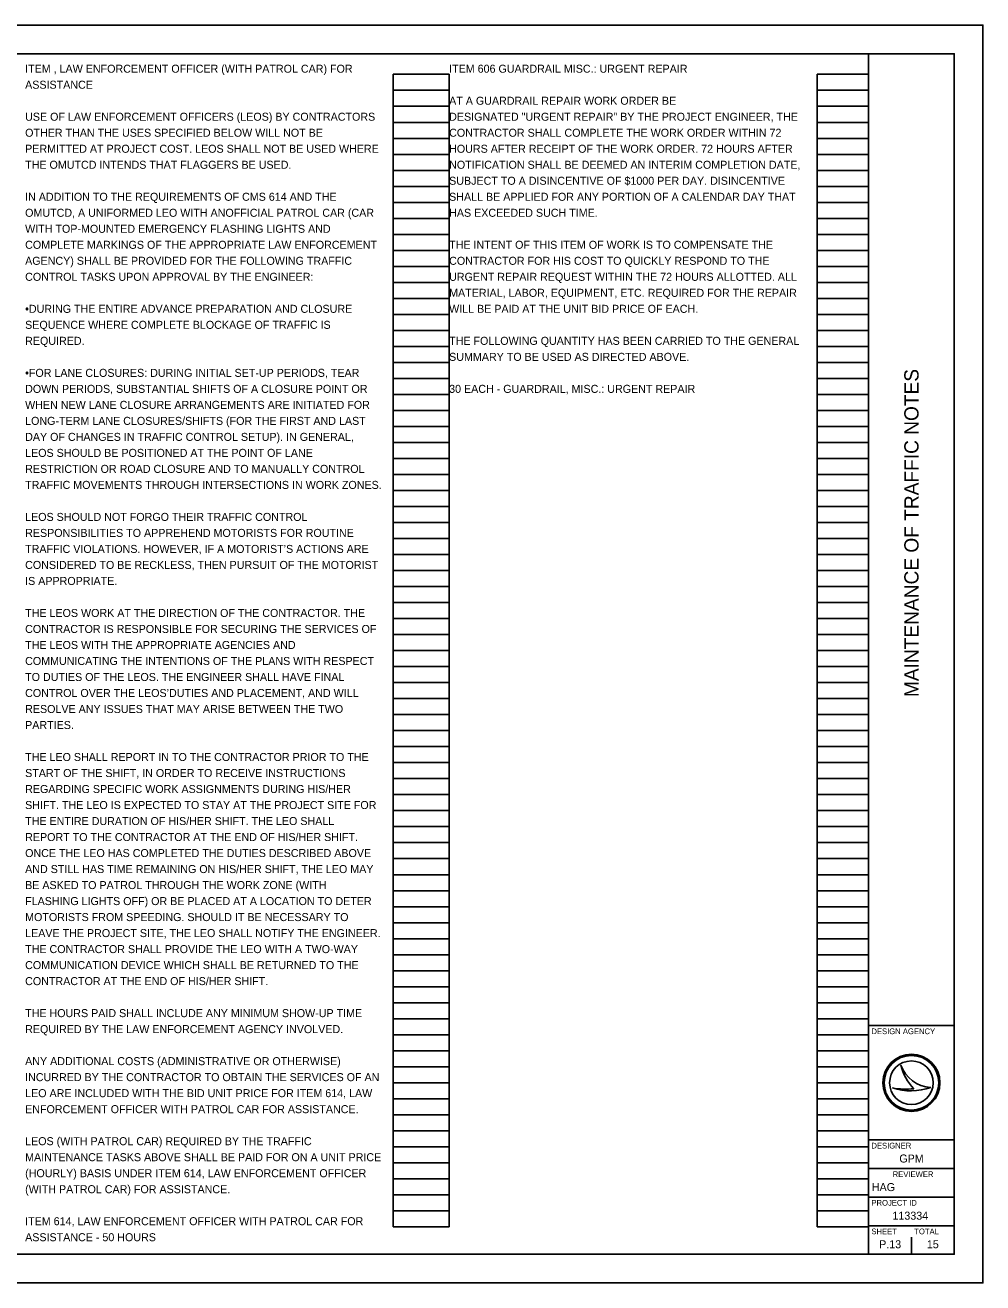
# Model space of a CAD drawing. Extents: x 0 to 34, y 0 to 22.
# Drawn here: x 17.24 to 34, y 0 to 22 of the extents above; entities that cross this region are included whole.
import ezdxf

# ---------------------------------------------------------------- set-up
doc = ezdxf.new("R2010")
doc.units = 0
for name, color, linetype in [('SH_Border', 7, 'Continuous'), ('SH_Cut_Line', 7, 'Continuous'), ('SH_Data', 7, 'Continuous'), ('SH_Text', 7, 'Continuous')]:
    doc.layers.add(name, color=color, linetype=linetype)

msp = doc.modelspace()

# ---------------------------------------------------------------- linework, layer by layer
at = {"layer": 'SH_Border'}
for p, q in [((32, 0.5), (32, 21.5)), ((32, 4.5), (33.5, 4.5)), ((32, 2.5), (33.5, 2.5)), ((32, 2), (33.5, 2)), ((32, 1.5), (33.5, 1.5)), ((32, 1), (33.5, 1))]:
    msp.add_line(p, q, dxfattribs=at)
msp.add_lwpolyline([(1.5, 21.5), (33.5, 21.5), (33.5, 0.5), (1.5, 0.5)], close=True, dxfattribs=at)
at = {"layer": 'SH_Cut_Line'}
msp.add_lwpolyline([(0, 0), (34, 0), (34, 22), (0, 22)], close=True, dxfattribs=at)
at = {"layer": 'SH_Data'}
for p, q in [((23.68, 0.98), (23.68, 21.14)), ((23.68, 21.14), (24.66, 21.14)), ((24.66, 0.98), (24.66, 21.14)), ((31.1, 0.98), (31.1, 21.14)), ((31.1, 21.14), (32, 21.14)), ((32, 0.98), (32, 21.14)), ((23.68, 20.86), (24.66, 20.86)), ((31.1, 20.86), (32, 20.86)), ((23.68, 20.58), (24.66, 20.58)), ((31.1, 20.58), (32, 20.58)), ((23.68, 20.3), (24.66, 20.3)), ((31.1, 20.3), (32, 20.3)), ((23.68, 20.02), (24.66, 20.02)), ((31.1, 20.02), (32, 20.02)), ((23.68, 19.74), (24.66, 19.74)), ((31.1, 19.74), (32, 19.74)), ((23.68, 19.46), (24.66, 19.46)), ((31.1, 19.46), (32, 19.46)), ((23.68, 19.18), (24.66, 19.18)), ((31.1, 19.18), (32, 19.18)), ((23.68, 18.9), (24.66, 18.9)), ((31.1, 18.9), (32, 18.9)), ((23.68, 18.62), (24.66, 18.62)), ((31.1, 18.62), (32, 18.62)), ((23.68, 18.34), (24.66, 18.34)), ((31.1, 18.34), (32, 18.34)), ((23.68, 18.06), (24.66, 18.06)), ((31.1, 18.06), (32, 18.06)), ((23.68, 17.78), (24.66, 17.78)), ((31.1, 17.78), (32, 17.78)), ((23.68, 17.5), (24.66, 17.5)), ((31.1, 17.5), (32, 17.5)), ((23.68, 17.22), (24.66, 17.22)), ((31.1, 17.22), (32, 17.22)), ((23.68, 16.94), (24.66, 16.94)), ((31.1, 16.94), (32, 16.94)), ((23.68, 16.66), (24.66, 16.66)), ((31.1, 16.66), (32, 16.66)), ((23.68, 16.38), (24.66, 16.38)), ((31.1, 16.38), (32, 16.38)), ((23.68, 16.1), (24.66, 16.1)), ((31.1, 16.1), (32, 16.1)), ((23.68, 15.82), (24.66, 15.82)), ((31.1, 15.82), (32, 15.82)), ((23.68, 15.54), (24.66, 15.54)), ((31.1, 15.54), (32, 15.54)), ((23.68, 15.26), (24.66, 15.26)), ((31.1, 15.26), (32, 15.26)), ((23.68, 14.98), (24.66, 14.98)), ((31.1, 14.98), (32, 14.98)), ((23.68, 14.7), (24.66, 14.7)), ((31.1, 14.7), (32, 14.7)), ((23.68, 14.42), (24.66, 14.42)), ((31.1, 14.42), (32, 14.42)), ((23.68, 14.14), (24.66, 14.14)), ((31.1, 14.14), (32, 14.14)), ((23.68, 13.86), (24.66, 13.86)), ((31.1, 13.86), (32, 13.86)), ((23.68, 13.58), (24.66, 13.58)), ((31.1, 13.58), (32, 13.58)), ((23.68, 13.3), (24.66, 13.3)), ((31.1, 13.3), (32, 13.3)), ((23.68, 13.02), (24.66, 13.02)), ((31.1, 13.02), (32, 13.02)), ((23.68, 12.74), (24.66, 12.74)), ((31.1, 12.74), (32, 12.74)), ((23.68, 12.46), (24.66, 12.46)), ((31.1, 12.46), (32, 12.46)), ((23.68, 12.18), (24.66, 12.18)), ((31.1, 12.18), (32, 12.18)), ((23.68, 11.9), (24.66, 11.9)), ((31.1, 11.9), (32, 11.9)), ((23.68, 11.62), (24.66, 11.62)), ((31.1, 11.62), (32, 11.62)), ((23.68, 11.34), (24.66, 11.34)), ((31.1, 11.34), (32, 11.34)), ((23.68, 11.06), (24.66, 11.06)), ((31.1, 11.06), (32, 11.06)), ((23.68, 10.78), (24.66, 10.78)), ((31.1, 10.78), (32, 10.78)), ((23.68, 10.5), (24.66, 10.5)), ((31.1, 10.5), (32, 10.5)), ((23.68, 10.22), (24.66, 10.22)), ((31.1, 10.22), (32, 10.22)), ((23.68, 9.94), (24.66, 9.94)), ((31.1, 9.94), (32, 9.94)), ((23.68, 9.66), (24.66, 9.66)), ((31.1, 9.66), (32, 9.66)), ((23.68, 9.38), (24.66, 9.38)), ((31.1, 9.38), (32, 9.38)), ((23.68, 9.1), (24.66, 9.1)), ((31.1, 9.1), (32, 9.1)), ((23.68, 8.82), (24.66, 8.82)), ((31.1, 8.82), (32, 8.82)), ((23.68, 8.54), (24.66, 8.54)), ((31.1, 8.54), (32, 8.54)), ((23.68, 8.26), (24.66, 8.26)), ((31.1, 8.26), (32, 8.26)), ((23.68, 7.98), (24.66, 7.98)), ((31.1, 7.98), (32, 7.98)), ((23.68, 7.7), (24.66, 7.7)), ((31.1, 7.7), (32, 7.7)), ((23.68, 7.42), (24.66, 7.42)), ((31.1, 7.42), (32, 7.42)), ((23.68, 7.14), (24.66, 7.14)), ((31.1, 7.14), (32, 7.14)), ((23.68, 6.86), (24.66, 6.86)), ((31.1, 6.86), (32, 6.86)), ((23.68, 6.58), (24.66, 6.58)), ((31.1, 6.58), (32, 6.58)), ((23.68, 6.3), (24.66, 6.3)), ((31.1, 6.3), (32, 6.3)), ((23.68, 6.02), (24.66, 6.02)), ((31.1, 6.02), (32, 6.02)), ((23.68, 5.74), (24.66, 5.74)), ((31.1, 5.74), (32, 5.74)), ((23.68, 5.46), (24.66, 5.46)), ((31.1, 5.46), (32, 5.46)), ((23.68, 5.18), (24.66, 5.18)), ((31.1, 5.18), (32, 5.18)), ((23.68, 4.9), (24.66, 4.9)), ((31.1, 4.9), (32, 4.9)), ((23.68, 4.62), (24.66, 4.62)), ((31.1, 4.62), (32, 4.62)), ((23.68, 4.34), (24.66, 4.34)), ((31.1, 4.34), (32, 4.34)), ((23.68, 4.06), (24.66, 4.06)), ((31.1, 4.06), (32, 4.06)), ((23.68, 3.78), (24.66, 3.78)), ((31.1, 3.78), (32, 3.78)), ((32.567, 3.81), (32.567, 3.81)), ((23.68, 3.5), (24.66, 3.5)), ((31.1, 3.5), (32, 3.5)), ((32.417, 3.41), (32.417, 3.41)), ((32.75, 3.5), (32.75, 3.5)), ((33.087, 3.419), (33.087, 3.419)), ((23.68, 3.22), (24.66, 3.22)), ((31.1, 3.22), (32, 3.22)), ((23.68, 2.94), (24.66, 2.94)), ((31.1, 2.94), (32, 2.94)), ((23.68, 2.66), (24.66, 2.66)), ((31.1, 2.66), (32, 2.66)), ((23.68, 2.38), (24.66, 2.38)), ((31.1, 2.38), (32, 2.38)), ((23.68, 2.1), (24.66, 2.1)), ((31.1, 2.1), (32, 2.1)), ((23.68, 1.82), (24.66, 1.82)), ((31.1, 1.82), (32, 1.82)), ((23.68, 1.54), (24.66, 1.54)), ((31.1, 1.54), (32, 1.54)), ((23.68, 1.26), (24.66, 1.26)), ((31.1, 1.26), (32, 1.26)), ((23.68, 0.98), (24.66, 0.98)), ((31.1, 0.98), (32, 0.98)), ((32.375, 0.675), (32.375, 0.675)), ((32.75, 0.5), (32.75, 0.8))]:
    msp.add_line(p, q, dxfattribs=at)
for radius in [0.5, 0.477, 0.477, 0.382]:
    msp.add_circle((32.75, 3.5), radius, dxfattribs=at)
for centre, radius, start, end in [((33.116, 3.998), 0.58, 198.9257, 198.9319), ((33.347, 3.97), 0.796, 191.6379, 191.6421), ((33.116, 3.998), 0.58, 198.9319, 267.1657), ((33.347, 3.97), 0.796, 191.6421, 226.0947), ((32.739, 4.37), 1.013, 251.4576, 290.0832), ((32.648, 4.654), 1.266, 259.4964, 259.4995), ((32.739, 4.37), 1.013, 251.4527, 251.4576), ((32.648, 4.654), 1.266, 259.4995, 276.6672)]:
    msp.add_arc(centre, radius, start, end, dxfattribs=at)

# ---------------------------------------------------------------- texts
msp.add_text('MAINTENANCE OF TRAFFIC NOTES', height=0.25, rotation=90, dxfattribs=at).set_placement((32.875, 10.247))
for s, height, p in [('DESIGN AGENCY', 0.1, (32.05, 4.35)), ('DESIGNER', 0.1, (32.05, 2.35)), ('GPM', 0.14, (32.538, 2.105)), ('REVIEWER', 0.1, (32.422, 1.85)), ('HAG', 0.14, (32.057, 1.605)), ('PROJECT ID', 0.1, (32.05, 1.35)), ('113334', 0.14, (32.418, 1.105)), ('SHEET', 0.1, (32.05, 0.85)), ('TOTAL', 0.1, (32.8, 0.85)), ('P.13', 0.14, (32.185, 0.605)), ('15', 0.14, (33.02, 0.605))]:
    msp.add_text(s, height=height, dxfattribs=at).set_placement(p)
at = {"layer": 'SH_Text'}
for s, p in [('ITEM , LAW ENFORCEMENT OFFICER (WITH PATROL CAR) FOR', (17.24, 21.168)), ('ITEM 606 GUARDRAIL MISC.: URGENT REPAIR', (24.66, 21.168)), ('ASSISTANCE', (17.24, 20.888)), ('AT A GUARDRAIL REPAIR WORK ORDER BE', (24.66, 20.608)), ('USE OF LAW ENFORCEMENT OFFICERS (LEOS) BY CONTRACTORS', (17.24, 20.328)), ('DESIGNATED "URGENT REPAIR" BY THE PROJECT ENGINEER, THE', (24.66, 20.328)), ('OTHER THAN THE USES SPECIFIED BELOW WILL NOT BE', (17.24, 20.048)), ('CONTRACTOR SHALL COMPLETE THE WORK ORDER WITHIN 72', (24.66, 20.048)), ('PERMITTED AT PROJECT COST. LEOS SHALL NOT BE USED WHERE', (17.24, 19.768)), ('HOURS AFTER RECEIPT OF THE WORK ORDER. 72 HOURS AFTER', (24.66, 19.768)), ('THE OMUTCD INTENDS THAT FLAGGERS BE USED.', (17.24, 19.488)), ('NOTIFICATION SHALL BE DEEMED AN INTERIM COMPLETION DATE,', (24.66, 19.488)), ('SUBJECT TO A DISINCENTIVE OF $1000 PER DAY. DISINCENTIVE', (24.66, 19.208)), ('IN ADDITION TO THE REQUIREMENTS OF CMS 614 AND THE', (17.24, 18.928)), ('SHALL BE APPLIED FOR ANY PORTION OF A CALENDAR DAY THAT', (24.66, 18.928)), ('OMUTCD, A UNIFORMED LEO WITH ANOFFICIAL PATROL CAR (CAR', (17.24, 18.648)), ('HAS EXCEEDED SUCH TIME.', (24.66, 18.648)), ('WITH TOP-MOUNTED EMERGENCY FLASHING LIGHTS AND', (17.24, 18.368)), ('COMPLETE MARKINGS OF THE APPROPRIATE LAW ENFORCEMENT', (17.24, 18.088)), ('THE INTENT OF THIS ITEM OF WORK IS TO COMPENSATE THE', (24.66, 18.088)), ('AGENCY) SHALL BE PROVIDED FOR THE FOLLOWING TRAFFIC', (17.24, 17.808)), ('CONTRACTOR FOR HIS COST TO QUICKLY RESPOND TO THE', (24.66, 17.808)), ('CONTROL TASKS UPON APPROVAL BY THE ENGINEER:', (17.24, 17.528)), ('URGENT REPAIR REQUEST WITHIN THE 72 HOURS ALLOTTED. ALL', (24.66, 17.528)), ('MATERIAL, LABOR, EQUIPMENT, ETC. REQUIRED FOR THE REPAIR', (24.66, 17.248)), ('•DURING THE ENTIRE ADVANCE PREPARATION AND CLOSURE', (17.24, 16.968)), ('WILL BE PAID AT THE UNIT BID PRICE OF EACH.', (24.66, 16.968)), ('SEQUENCE WHERE COMPLETE BLOCKAGE OF TRAFFIC IS', (17.24, 16.688)), ('REQUIRED.', (17.24, 16.408)), ('THE FOLLOWING QUANTITY HAS BEEN CARRIED TO THE GENERAL', (24.66, 16.408)), ('SUMMARY TO BE USED AS DIRECTED ABOVE.', (24.66, 16.128)), ('•FOR LANE CLOSURES: DURING INITIAL SET-UP PERIODS, TEAR', (17.24, 15.848)), ('DOWN PERIODS, SUBSTANTIAL SHIFTS OF A CLOSURE POINT OR', (17.24, 15.568)), ('30 EACH - GUARDRAIL, MISC.: URGENT REPAIR', (24.66, 15.568)), ('WHEN NEW LANE CLOSURE ARRANGEMENTS ARE INITIATED FOR', (17.24, 15.288)), ('LONG-TERM LANE CLOSURES/SHIFTS (FOR THE FIRST AND LAST', (17.24, 15.008)), ('DAY OF CHANGES IN TRAFFIC CONTROL SETUP). IN GENERAL,', (17.24, 14.728)), ('LEOS SHOULD BE POSITIONED AT THE POINT OF LANE', (17.24, 14.448)), ('RESTRICTION OR ROAD CLOSURE AND TO MANUALLY CONTROL', (17.24, 14.168)), ('TRAFFIC MOVEMENTS THROUGH INTERSECTIONS IN WORK ZONES.', (17.24, 13.888)), ('LEOS SHOULD NOT FORGO THEIR TRAFFIC CONTROL', (17.24, 13.328)), ('RESPONSIBILITIES TO APPREHEND MOTORISTS FOR ROUTINE', (17.24, 13.048)), ('TRAFFIC VIOLATIONS. HOWEVER, IF A MOTORIST’S ACTIONS ARE', (17.24, 12.768)), ('CONSIDERED TO BE RECKLESS, THEN PURSUIT OF THE MOTORIST', (17.24, 12.488)), ('IS APPROPRIATE.', (17.24, 12.208)), ('THE LEOS WORK AT THE DIRECTION OF THE CONTRACTOR. THE', (17.24, 11.648)), ('CONTRACTOR IS RESPONSIBLE FOR SECURING THE SERVICES OF', (17.24, 11.368)), ('THE LEOS WITH THE APPROPRIATE AGENCIES AND', (17.24, 11.088)), ('COMMUNICATING THE INTENTIONS OF THE PLANS WITH RESPECT', (17.24, 10.808)), ('TO DUTIES OF THE LEOS. THE ENGINEER SHALL HAVE FINAL', (17.24, 10.528)), ('CONTROL OVER THE LEOS’DUTIES AND PLACEMENT, AND WILL', (17.24, 10.248)), ('RESOLVE ANY ISSUES THAT MAY ARISE BETWEEN THE TWO', (17.24, 9.968)), ('PARTIES.', (17.24, 9.688)), ('THE LEO SHALL REPORT IN TO THE CONTRACTOR PRIOR TO THE', (17.24, 9.128)), ('START OF THE SHIFT, IN ORDER TO RECEIVE INSTRUCTIONS', (17.24, 8.848)), ('REGARDING SPECIFIC WORK ASSIGNMENTS DURING HIS/HER', (17.24, 8.568)), ('SHIFT. THE LEO IS EXPECTED TO STAY AT THE PROJECT SITE FOR', (17.24, 8.288)), ('THE ENTIRE DURATION OF HIS/HER SHIFT. THE LEO SHALL', (17.24, 8.008)), ('REPORT TO THE CONTRACTOR AT THE END OF HIS/HER SHIFT.', (17.24, 7.728)), ('ONCE THE LEO HAS COMPLETED THE DUTIES DESCRIBED ABOVE', (17.24, 7.448)), ('AND STILL HAS TIME REMAINING ON HIS/HER SHIFT, THE LEO MAY', (17.24, 7.168)), ('BE ASKED TO PATROL THROUGH THE WORK ZONE (WITH', (17.24, 6.888)), ('FLASHING LIGHTS OFF) OR BE PLACED AT A LOCATION TO DETER', (17.24, 6.608)), ('MOTORISTS FROM SPEEDING. SHOULD IT BE NECESSARY TO', (17.24, 6.328)), ('LEAVE THE PROJECT SITE, THE LEO SHALL NOTIFY THE ENGINEER.', (17.24, 6.048)), ('THE CONTRACTOR SHALL PROVIDE THE LEO WITH A TWO-WAY', (17.24, 5.768)), ('COMMUNICATION DEVICE WHICH SHALL BE RETURNED TO THE', (17.24, 5.488)), ('CONTRACTOR AT THE END OF HIS/HER SHIFT.', (17.24, 5.208)), ('THE HOURS PAID SHALL INCLUDE ANY MINIMUM SHOW-UP TIME', (17.24, 4.648)), ('REQUIRED BY THE LAW ENFORCEMENT AGENCY INVOLVED.', (17.24, 4.368)), ('ANY ADDITIONAL COSTS (ADMINISTRATIVE OR OTHERWISE)', (17.24, 3.808)), ('INCURRED BY THE CONTRACTOR TO OBTAIN THE SERVICES OF AN', (17.24, 3.528)), ('LEO ARE INCLUDED WITH THE BID UNIT PRICE FOR ITEM 614, LAW', (17.24, 3.248)), ('ENFORCEMENT OFFICER WITH PATROL CAR FOR ASSISTANCE.', (17.24, 2.968)), ('LEOS (WITH PATROL CAR) REQUIRED BY THE TRAFFIC', (17.24, 2.408)), ('MAINTENANCE TASKS ABOVE SHALL BE PAID FOR ON A UNIT PRICE', (17.24, 2.128)), ('(HOURLY) BASIS UNDER ITEM 614, LAW ENFORCEMENT OFFICER', (17.24, 1.848)), ('(WITH PATROL CAR) FOR ASSISTANCE.', (17.24, 1.568)), ('ITEM 614, LAW ENFORCEMENT OFFICER WITH PATROL CAR FOR', (17.24, 1.008)), ('ASSISTANCE - 50 HOURS', (17.24, 0.728))]:
    msp.add_text(s, height=0.14, dxfattribs=at).set_placement(p)

doc.saveas('drawing.dxf')
